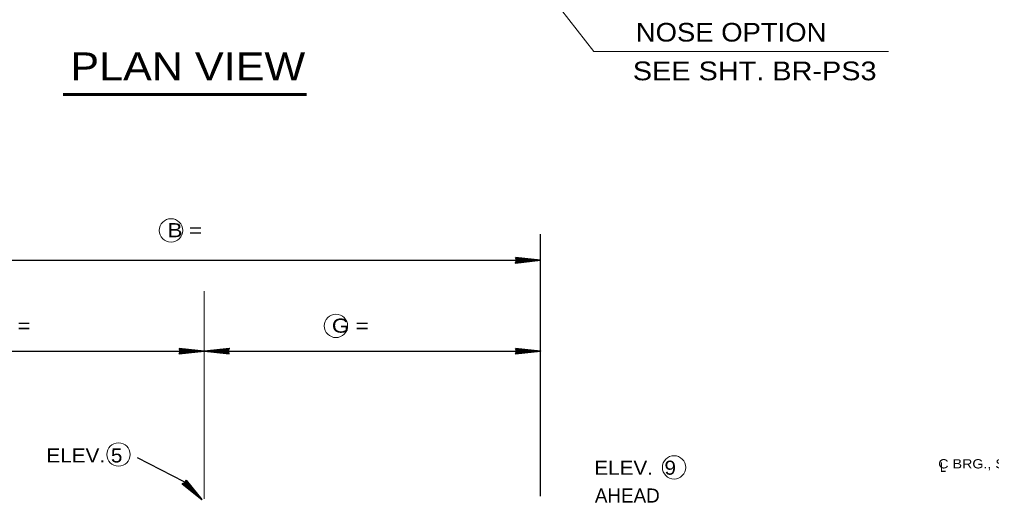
# Model space of a CAD drawing. Extents: x 1.6 to 19.9, y 2.8 to 9.5.
# Drawn here: x 16.884 to 17.696, y 8.342 to 8.746 of the extents above; entities that cross this region are included whole.
import ezdxf

# ---------------------------------------------------------------- set-up
doc = ezdxf.new("R2010")
doc.units = 0
doc.header["$LTSCALE"] = 0.0047
doc.layers.add('1', color=7, linetype='Continuous', lineweight=35)
doc.layers.add('5', color=7, linetype='Continuous', lineweight=13)

msp = doc.modelspace()

# ---------------------------------------------------------------- linework, layer by layer
at = {"layer": '1', "lineweight": 13}
for p, q in [((17.364083, 8.719), (17.29675, 8.805333)), ((17.364083, 8.719), (17.610083, 8.719)), ((17.038667, 8.51875), (17.038667, 8.345333))]:
    msp.add_line(p, q, dxfattribs=at)
at = {"layer": '1', "lineweight": 60}
msp.add_line((17.124167, 8.68325), (16.921, 8.68325), dxfattribs=at)
at = {"layer": '1', "lineweight": 25}
for p, q in [((17.3195, 8.347667), (17.3195, 8.5665)), ((16.75075, 8.46875), (17.3195, 8.46875))]:
    msp.add_line(p, q, dxfattribs=at)
at = {"layer": '1'}
for p, q in [((17.298583, 8.54475), (17.319417, 8.54475)), ((17.298917, 8.546667), (17.3145, 8.545)), ((17.298917, 8.546583), (17.3145, 8.544833)), ((17.298917, 8.5465), (17.3145, 8.54475)), ((17.298917, 8.54625), (17.3145, 8.5445)), ((17.298917, 8.543417), (17.313417, 8.545)), ((17.298917, 8.543167), (17.313417, 8.54475)), ((17.298917, 8.542917), (17.3135, 8.5445)), ((17.299, 8.54675), (17.3145, 8.545)), ((17.299, 8.542667), (17.3135, 8.544333)), ((17.01775, 8.46875), (17.038667, 8.46875)), ((17.018083, 8.4675), (17.032667, 8.469)), ((17.018167, 8.47075), (17.033667, 8.469)), ((17.018167, 8.470667), (17.033667, 8.468917)), ((17.018167, 8.470583), (17.033667, 8.468833)), ((17.018167, 8.470333), (17.033667, 8.468583)), ((17.018167, 8.46725), (17.032667, 8.46875)), ((17.018167, 8.467), (17.032667, 8.4685)), ((17.01825, 8.47075), (17.033667, 8.469083)), ((17.01825, 8.46675), (17.032667, 8.468417)), ((17.0595, 8.46875), (17.038833, 8.46875)), ((17.059167, 8.46725), (17.043667, 8.468833)), ((17.059, 8.467), (17.043667, 8.46875)), ((17.059, 8.46675), (17.043667, 8.4685)), ((17.059, 8.466833), (17.043667, 8.4685)), ((17.059, 8.466917), (17.043667, 8.4685)), ((17.059, 8.47075), (17.044667, 8.469167)), ((17.059, 8.470583), (17.044667, 8.469)), ((17.059167, 8.470333), (17.04475, 8.46875)), ((17.059167, 8.470083), (17.04475, 8.4685)), ((17.298667, 8.46875), (17.3195, 8.46875)), ((17.298917, 8.4675), (17.3135, 8.469)), ((17.299, 8.47075), (17.314583, 8.469)), ((17.299, 8.470667), (17.314583, 8.468917)), ((17.299, 8.470583), (17.314583, 8.468833)), ((17.299, 8.470333), (17.314583, 8.468583)), ((17.299, 8.46725), (17.3135, 8.46875)), ((17.299, 8.467), (17.313583, 8.4685)), ((17.299167, 8.47075), (17.314583, 8.469083)), ((17.299167, 8.46675), (17.313583, 8.468417)), ((17.020833, 8.35775), (17.03225, 8.34875)), ((17.021, 8.357917), (17.032333, 8.34875)), ((17.021167, 8.35825), (17.032667, 8.349167)), ((17.021167, 8.358167), (17.032417, 8.349)), ((17.021917, 8.3595), (17.036667, 8.34475)), ((17.023333, 8.360333), (17.033083, 8.348167)), ((17.0235, 8.3605), (17.03325, 8.34825)), ((17.023583, 8.360583), (17.033333, 8.34825)), ((17.023667, 8.360583), (17.033417, 8.3485)), ((17.023667, 8.360583), (17.033417, 8.348417))]:
    msp.add_line(p, q, dxfattribs=at)
at = {"layer": '1', "lineweight": 25}
msp.add_lwpolyline([(16.75075, 8.54475), (17.049167, 8.54475), (17.317583, 8.54475)], dxfattribs=at)
at = {"layer": '1'}
for points in [[(17.298583, 8.547), (17.319417, 8.54475), (17.298583, 8.542333), (17.299667, 8.54475)], [(17.01775, 8.471), (17.038667, 8.46875), (17.01775, 8.466417), (17.018917, 8.46875)], [(17.0595, 8.4665), (17.038833, 8.46875), (17.0595, 8.471083), (17.058417, 8.46875)], [(17.298667, 8.471), (17.3195, 8.46875), (17.298667, 8.466417), (17.29975, 8.46875)], [(17.023583, 8.361083), (17.036667, 8.34475), (17.02025, 8.357833), (17.022667, 8.35875)]]:
    msp.add_lwpolyline(points, close=True, dxfattribs=at)
for points in [[(17.299917, 8.545), (17.30925, 8.545083), (17.309167, 8.544833), (17.307417, 8.545), (17.299917, 8.545083), (17.306, 8.54525), (17.29975, 8.545417), (17.304, 8.545583), (17.2995, 8.54575), (17.306667, 8.54525), (17.315917, 8.544833), (17.314, 8.544333), (17.316667, 8.5445), (17.299917, 8.5445), (17.304833, 8.544167), (17.29975, 8.544167), (17.31025, 8.544833), (17.299583, 8.54375), (17.300083, 8.544833), (17.299167, 8.546333), (17.299583, 8.546), (17.300083, 8.54525), (17.3005, 8.5455), (17.300167, 8.546083), (17.299833, 8.544667), (17.299417, 8.54375), (17.299, 8.54275)], [(17.019167, 8.469), (17.0285, 8.469167), (17.028417, 8.468917), (17.026667, 8.469), (17.019167, 8.469167), (17.025167, 8.469333), (17.018917, 8.4695), (17.02325, 8.469667), (17.018667, 8.469833), (17.025917, 8.469333), (17.035167, 8.468917), (17.03325, 8.468417), (17.035833, 8.468583), (17.019167, 8.4685), (17.024, 8.46825), (17.018917, 8.46825), (17.0295, 8.468917), (17.018833, 8.467833), (17.01925, 8.468917), (17.018333, 8.470417), (17.018833, 8.470083), (17.01925, 8.469333), (17.01975, 8.4695), (17.019333, 8.470167), (17.019, 8.46875), (17.018667, 8.467833), (17.01825, 8.466833)], [(17.058083, 8.4685), (17.048917, 8.468417), (17.048917, 8.468583), (17.050667, 8.4685), (17.058083, 8.468417), (17.052167, 8.46825), (17.058333, 8.468083), (17.053917, 8.467917), (17.0585, 8.467667), (17.051417, 8.46825), (17.04225, 8.468583), (17.044167, 8.469167), (17.041667, 8.468917), (17.058083, 8.469), (17.05325, 8.469333), (17.058333, 8.469333), (17.04775, 8.4685), (17.058417, 8.46975), (17.058, 8.4685), (17.058917, 8.467167), (17.058417, 8.4675), (17.058, 8.46825), (17.057417, 8.468), (17.057917, 8.467333), (17.058167, 8.468833), (17.058583, 8.46975), (17.059, 8.47075)], [(17.300083, 8.469), (17.309333, 8.469167), (17.30925, 8.468917), (17.307583, 8.469), (17.300083, 8.469167), (17.306083, 8.469333), (17.299833, 8.4695), (17.304167, 8.469667), (17.299583, 8.469833), (17.30675, 8.469333), (17.316, 8.468917), (17.314167, 8.468417), (17.316667, 8.468583), (17.300083, 8.4685), (17.304917, 8.46825), (17.299833, 8.46825), (17.310417, 8.468917), (17.299667, 8.467833), (17.300167, 8.468917), (17.299167, 8.470417), (17.299667, 8.470083), (17.300167, 8.469333), (17.300583, 8.4695), (17.300167, 8.470167), (17.299917, 8.46875), (17.2995, 8.467833), (17.299167, 8.466833)], [(17.023083, 8.35875), (17.029833, 8.35225), (17.029583, 8.352), (17.028417, 8.353417), (17.02325, 8.35875), (17.027667, 8.354667), (17.02325, 8.359167), (17.026417, 8.35625), (17.023417, 8.359667), (17.028083, 8.354167), (17.034333, 8.347333), (17.032667, 8.34825), (17.034583, 8.346583), (17.02275, 8.35825), (17.026, 8.35475), (17.022417, 8.35825), (17.030417, 8.351333), (17.022, 8.358167), (17.023083, 8.3585), (17.0235, 8.36025), (17.023667, 8.35975), (17.023417, 8.358833), (17.023917, 8.35875), (17.024, 8.359417), (17.02275, 8.3585), (17.021917, 8.35825), (17.020917, 8.35775)]]:
    msp.add_lwpolyline(points, dxfattribs=at)
at = {"layer": '1', "lineweight": 13}
for centre in [(17.01093, 8.569595), (17.148664, 8.489829), (16.967102, 8.382408), (17.431008, 8.371626)]:
    msp.add_circle(centre, 0.009766, dxfattribs=at)
at = {"layer": '5', "lineweight": 25}
msp.add_line((17.021917, 8.3595), (16.982917, 8.37975), dxfattribs=at)

# ---------------------------------------------------------------- texts
at = {"layer": '1'}
for s, height, width, p in [('PLAN VIEW', 0.02342, 1.15, (16.926833, 8.694833)), ('ELEV. 5', 0.01175, 1.1, (16.906917, 8.37575)), ('C BRG., SPAN BEHIND', 0.00775, 1.15, (17.651667, 8.37075)), ('L', 0.007833, 0.85, (17.65325, 8.367917))]:
    msp.add_text(s, height=height, dxfattribs=dict(at, width=width)).set_placement(p)
at = {"layer": '5'}
for s, height, width, p in [('NOSE OPTION', 0.01558, 1.1, (17.399083, 8.727333)), ('SEE SHT. BR-PS3', 0.01567, 1.15, (17.396583, 8.695)), ('B =      ', 0.01175, 1.2, (17.008, 8.563917)), ('F =      ', 0.01175, 1.2, (16.865917, 8.484167)), ('G =      ', 0.01175, 1.2, (17.14525, 8.484167)), ('ELEV.  9', 0.01175, 1.1, (17.364417, 8.3655))]:
    msp.add_text(s, height=height, dxfattribs=dict(at, width=width)).set_placement(p)
msp.add_text('AHEAD', height=0.01175, dxfattribs=at).set_placement((17.364917, 8.34225))

doc.saveas('drawing.dxf')
